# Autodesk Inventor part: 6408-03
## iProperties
Author: Administrator
Shininess: 64.0
Angle Display Precision: 2
Document Length Units: 11272
Document Angle Units: 11286
Document Time Units: 11279
Document Mass Units: 11290
Document Length Units Precision: 3
Document Angle Units Precision: 2
Compacted: True
PropertySet Name: _Private Model Information
Created: 2001-12
Part Number: 6408-03
Description: Oring Male Plug (-3)
Document SubType Name: Modeling
Designer: Administrator
Control State: 0
Master: False
Checked Out: False
PropertySet Name: Design Tracking Control
Density: 0.0
Volumn: 0.0
Area: 0.0
PropertySet Name: Model Information
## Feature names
1. Extrusion1
2. Extrusion2
3. Revolution1
4. Chamfer1
5. Revolution2
